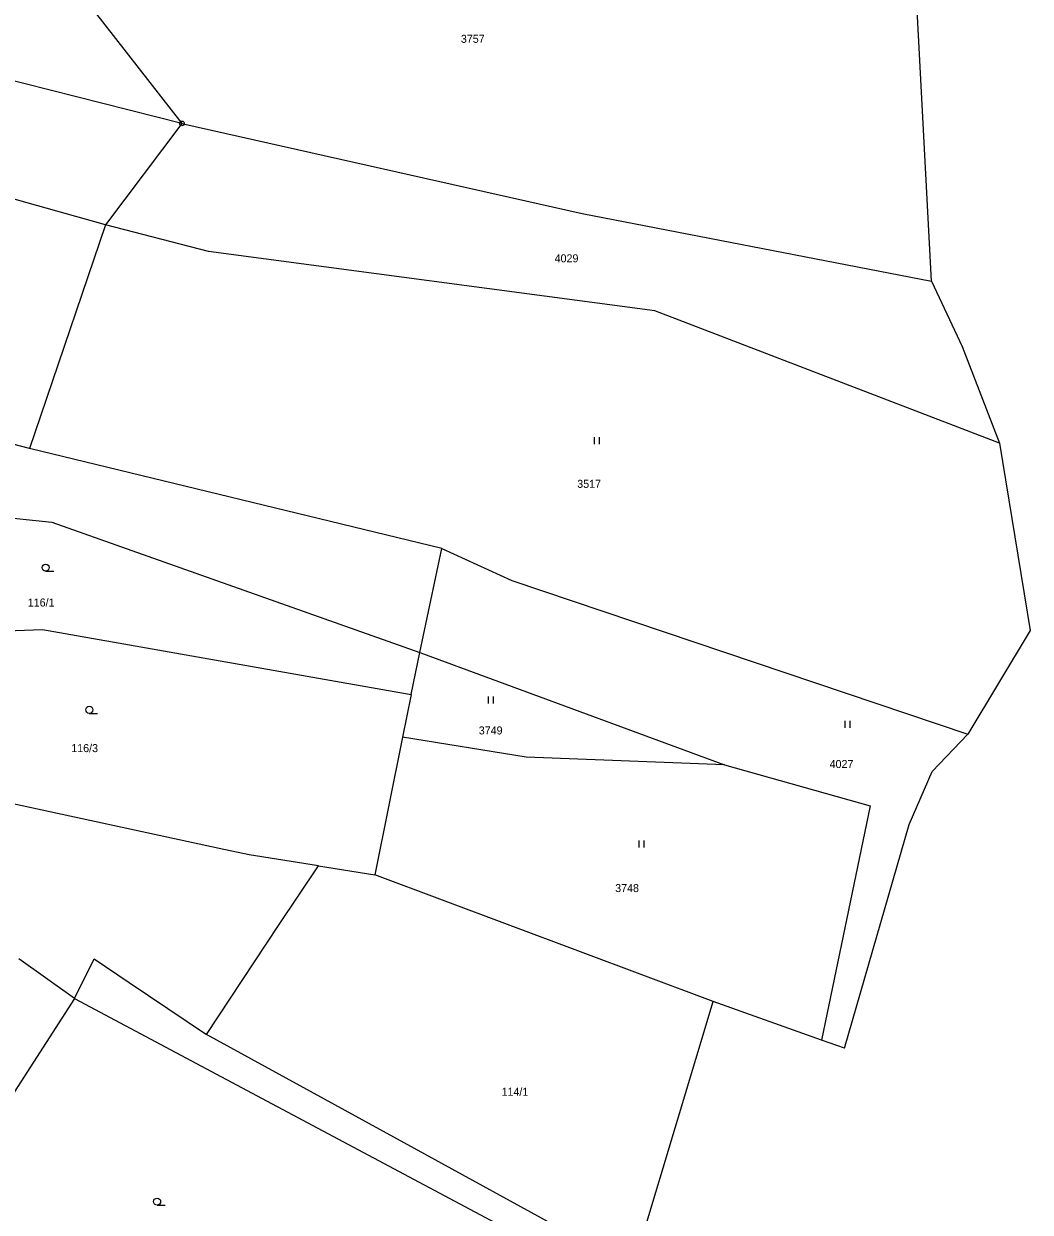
# Model space of a CAD drawing. Extents: x -717366 to -716792, y -1145485 to -1142762.
# Drawn here: x -717079.2 to -716972.3, y -1144332.4 to -1144206.1 of the extents above; entities that cross this region are included whole.
import ezdxf

# ---------------------------------------------------------------- set-up
doc = ezdxf.new("R2010")
doc.units = 0
doc.layers.add('Vrstva 1', color=7, linetype='Continuous')

msp = doc.modelspace()

# ---------------------------------------------------------------- linework, layer by layer
at = {"layer": 'Vrstva 1'}
for p, q in [((-716982.77, -1144233.47), (-716984.63, -1144197.63)), ((-717076.19, -1144198.99), (-717062.39, -1144216.7)), ((-717062.39, -1144216.7), (-717100.72, -1144207.05)), ((-717062.39, -1144216.7), (-717070.49, -1144227.47)), ((-717062.39, -1144216.7), (-717019.88, -1144226.28)), ((-717070.49, -1144227.47), (-717100.75, -1144219.01)), ((-717019.88, -1144226.28), (-716982.77, -1144233.47)), ((-717070.49, -1144227.47), (-717077.4, -1144247.79)), ((-717059.55, -1144230.32), (-717070.49, -1144227.47)), ((-717012.13, -1144236.62), (-717059.55, -1144230.32)), ((-716982.77, -1144233.47), (-716979.49, -1144240.4)), ((-716975.52, -1144250.67), (-717012.13, -1144236.62)), ((-716979.49, -1144240.4), (-716975.52, -1144250.67)), ((-717078.58, -1144251.25), (-717101.12, -1144245.42)), ((-717077.4, -1144247.79), (-717078.58, -1144251.25)), ((-717018.57, -1144250.79), (-717018.57, -1144250.04)), ((-717018.07, -1144250.04), (-717018.07, -1144250.79)), ((-716975.52, -1144250.67), (-716972.27, -1144270.59)), ((-717034.77, -1144261.88), (-717078.58, -1144251.25)), ((-717099.59, -1144256.57), (-717076.2, -1144259.08)), ((-717076.2, -1144259.08), (-717037.1, -1144272.91)), ((-717037.1, -1144272.91), (-717034.77, -1144261.88)), ((-717034.77, -1144261.88), (-717027.32, -1144265.27)), ((-717076.86, -1144264.27), (-717075.985, -1144264.27)), ((-717027.32, -1144265.27), (-716978.91, -1144281.58)), ((-717103.36, -1144271.54), (-717077.19, -1144270.46)), ((-717077.19, -1144270.46), (-717038.04, -1144277.38)), ((-716972.27, -1144270.59), (-716978.91, -1144281.58)), ((-717038.04, -1144277.38), (-717037.1, -1144272.91)), ((-717037.1, -1144272.91), (-717004.75, -1144284.86)), ((-717038.04, -1144277.38), (-717038.95, -1144281.92)), ((-717029.83, -1144278.35), (-717029.83, -1144277.6)), ((-717029.33, -1144277.6), (-717029.33, -1144278.35)), ((-717072.22, -1144279.38), (-717071.345, -1144279.38)), ((-716991.93, -1144280.92), (-716991.93, -1144280.17)), ((-716991.43, -1144280.17), (-716991.43, -1144280.92)), ((-717038.95, -1144281.92), (-717041.89, -1144296.52)), ((-717025.82, -1144284.05), (-717038.95, -1144281.92)), ((-716982.69, -1144285.56), (-716978.91, -1144281.58)), ((-717004.75, -1144284.86), (-717025.82, -1144284.05)), ((-717004.75, -1144284.86), (-716989.26, -1144289.21)), ((-716985.13, -1144291.19), (-716982.69, -1144285.56)), ((-717058.42, -1144293.74), (-717083.08, -1144288.4)), ((-716989.26, -1144289.21), (-716994.45, -1144314.1)), ((-716992.01, -1144314.97), (-716985.13, -1144291.19)), ((-717055.23, -1144294.4), (-717058.42, -1144293.74)), ((-717013.81, -1144293.65), (-717013.81, -1144292.9)), ((-717013.31, -1144292.9), (-717013.31, -1144293.65)), ((-717047.88, -1144295.57), (-717055.23, -1144294.4)), ((-717052.14, -1144301.92), (-717047.88, -1144295.57)), ((-717047.88, -1144295.57), (-717041.89, -1144296.52)), ((-717005.94, -1144310.01), (-717041.89, -1144296.52)), ((-717059.76, -1144313.5), (-717052.14, -1144301.92)), ((-717073.79, -1144309.69), (-717079.69, -1144305.48)), ((-717073.79, -1144309.69), (-717071.69, -1144305.48)), ((-717071.69, -1144305.48), (-717067.99, -1144307.97)), ((-717067.99, -1144307.97), (-717059.76, -1144313.5)), ((-717073.79, -1144309.69), (-717081.17, -1144321.11)), ((-717073.79, -1144309.69), (-716979.42, -1144359.93)), ((-717014.48, -1144338.33), (-717005.94, -1144310.01)), ((-716994.45, -1144314.1), (-717005.94, -1144310.01)), ((-717038.78, -1144325.01), (-717059.76, -1144313.5)), ((-716992.01, -1144314.97), (-716994.45, -1144314.1)), ((-717014.48, -1144338.33), (-717038.78, -1144325.01)), ((-717065.02, -1144331.63), (-717064.145, -1144331.63))]:
    msp.add_line(p, q, dxfattribs=at)
for centre, radius in [((-717062.39, -1144216.7), 0.25), ((-717062.39, -1144216.7), 0.25), ((-717062.39, -1144216.7), 0.005), ((-717062.39, -1144216.7), 0.005), ((-717076.86, -1144263.895), 0.375), ((-717072.22, -1144279.005), 0.375), ((-717065.02, -1144331.255), 0.375)]:
    msp.add_circle(centre, radius, dxfattribs=at)

# ---------------------------------------------------------------- texts
for s, p in [('3757', (-717032.75, -1144208.14)), ('4029', (-717022.79, -1144231.46)), ('3517', (-717020.39, -1144255.42)), ('116/1', (-717078.76, -1144268.03)), ('3749', (-717030.85, -1144281.62)), ('116/3', (-717074.14, -1144283.5)), ('4027', (-716993.58, -1144285.19)), ('3748', (-717016.36, -1144298.37)), ('114/1', (-717028.43, -1144320.01))]:
    msp.add_text(s, height=0.85, dxfattribs=at).set_placement(p)

doc.saveas('drawing.dxf')
